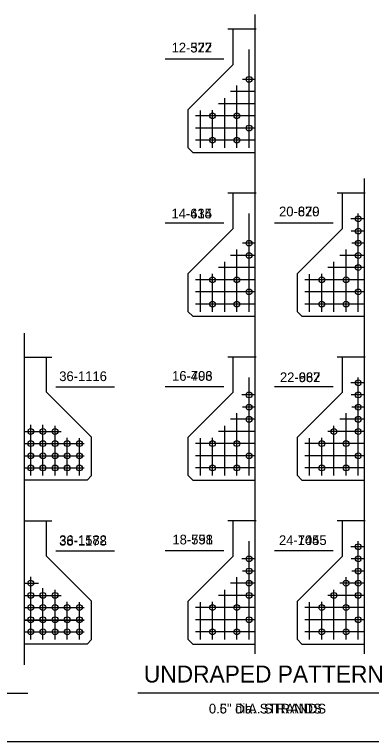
# Model space of a CAD drawing. Extents: x 1005.3 to 1101.9, y 1996.5 to 2073.3.
# Drawn here: x 1025.64 to 1037.89, y 2012.16 to 2037.11 of the extents above; entities that cross this region are included whole.
import ezdxf

# ---------------------------------------------------------------- set-up
doc = ezdxf.new("R2010")
doc.units = 0
for name, color, linetype in [('Level 1', 7, 'Continuous'), ('Level 2', 7, 'Continuous'), ('Level 8', 7, 'Continuous'), ('Level 9', 7, 'Continuous')]:
    doc.layers.add(name, color=color, linetype=linetype)

msp = doc.modelspace()

# ---------------------------------------------------------------- linework, layer by layer
at = {"layer": 'Level 1'}
msp.add_line((1013.852, 2012.158), (1097.517, 2012.158), dxfattribs=at)
at = {"layer": 'Level 2'}
for p, q in [((1017.555, 2013.82), (1026.098, 2013.82)), ((1039.275, 2013.82), (1029.876, 2013.82))]:
    msp.add_line(p, q, dxfattribs=at)
at = {"layer": 'Level 8'}
for p, q in [((1033.897, 2015.162), (1033.897, 2037.107)), ((1033.929, 2036.601), (1032.963, 2036.601)), ((1033.144, 2035.393), (1033.144, 2036.594)), ((1033.687, 2032.533), (1033.687, 2035.904)), ((1032.827, 2035.577), (1030.807, 2035.577)), ((1031.599, 2033.848), (1033.144, 2035.393)), ((1033.905, 2034.882), (1033.468, 2034.882)), ((1033.905, 2034.882), (1033.902, 2034.882)), ((1033.269, 2032.533), (1033.269, 2034.673)), ((1033.905, 2034.464), (1033.053, 2034.464)), ((1032.852, 2032.533), (1032.852, 2034.242)), ((1031.599, 2032.533), (1031.599, 2033.848)), ((1033.905, 2034.047), (1032.641, 2034.047)), ((1033.905, 2033.629), (1031.849, 2033.629)), ((1032.017, 2032.533), (1032.017, 2033.819)), ((1032.434, 2032.533), (1032.434, 2033.827)), ((1033.905, 2033.212), (1031.849, 2033.212)), ((1033.905, 2032.794), (1031.849, 2032.794)), ((1031.755, 2032.376), (1031.599, 2032.533)), ((1031.755, 2032.376), (1033.905, 2032.376)), ((1037.655, 2015.162), (1037.655, 2031.484)), ((1033.929, 2030.976), (1032.963, 2030.976)), ((1033.144, 2029.768), (1033.144, 2030.969)), ((1037.679, 2030.976), (1036.713, 2030.976)), ((1036.894, 2029.768), (1036.894, 2030.969)), ((1033.687, 2026.908), (1033.687, 2030.279)), ((1037.655, 2030.092), (1037.187, 2030.092)), ((1037.437, 2026.908), (1037.437, 2030.279)), ((1032.827, 2029.952), (1030.807, 2029.952)), ((1036.577, 2029.952), (1034.557, 2029.952)), ((1031.599, 2028.223), (1033.144, 2029.768)), ((1035.349, 2028.223), (1036.894, 2029.768)), ((1037.655, 2029.675), (1037.19, 2029.675)), ((1033.905, 2029.257), (1033.468, 2029.257)), ((1033.905, 2029.257), (1033.902, 2029.257)), ((1037.655, 2029.257), (1037.218, 2029.257)), ((1037.655, 2029.257), (1037.652, 2029.257)), ((1033.269, 2026.908), (1033.269, 2029.048)), ((1037.019, 2026.908), (1037.019, 2029.048)), ((1032.852, 2026.908), (1032.852, 2028.617)), ((1033.905, 2028.839), (1033.053, 2028.839)), ((1036.602, 2026.908), (1036.602, 2028.617)), ((1037.655, 2028.839), (1036.803, 2028.839)), ((1033.905, 2028.422), (1032.641, 2028.422)), ((1037.655, 2028.422), (1036.391, 2028.422)), ((1031.599, 2026.908), (1031.599, 2028.223)), ((1032.017, 2026.908), (1032.017, 2028.194)), ((1032.434, 2026.908), (1032.434, 2028.202)), ((1035.349, 2026.908), (1035.349, 2028.223)), ((1035.767, 2026.908), (1035.767, 2028.194)), ((1036.184, 2026.908), (1036.184, 2028.202)), ((1033.905, 2028.004), (1031.849, 2028.004)), ((1037.655, 2028.004), (1035.599, 2028.004)), ((1033.905, 2027.587), (1031.849, 2027.587)), ((1037.655, 2027.587), (1035.599, 2027.587)), ((1033.905, 2027.169), (1031.849, 2027.169)), ((1037.655, 2027.169), (1035.599, 2027.169)), ((1031.755, 2026.751), (1031.599, 2026.908)), ((1035.505, 2026.751), (1035.349, 2026.908)), ((1031.755, 2026.751), (1033.905, 2026.751)), ((1035.505, 2026.751), (1037.655, 2026.751)), ((1025.976, 2015.057), (1025.976, 2026.174)), ((1025.953, 2025.351), (1026.918, 2025.351)), ((1033.929, 2025.351), (1032.963, 2025.351)), ((1037.679, 2025.351), (1036.713, 2025.351)), ((1026.738, 2024.143), (1026.738, 2025.344)), ((1033.144, 2024.143), (1033.144, 2025.344)), ((1036.894, 2024.143), (1036.894, 2025.344)), ((1033.687, 2021.283), (1033.687, 2024.654)), ((1037.437, 2021.283), (1037.437, 2024.654)), ((1037.655, 2024.467), (1037.187, 2024.467)), ((1028.282, 2022.598), (1026.738, 2024.143)), ((1027.054, 2024.327), (1029.074, 2024.327)), ((1032.827, 2024.327), (1030.807, 2024.327)), ((1031.599, 2022.598), (1033.144, 2024.143)), ((1036.577, 2024.327), (1034.557, 2024.327)), ((1035.349, 2022.598), (1036.894, 2024.143)), ((1033.905, 2024.05), (1033.44, 2024.05)), ((1037.655, 2024.05), (1037.19, 2024.05)), ((1033.905, 2023.632), (1033.468, 2023.632)), ((1033.905, 2023.632), (1033.902, 2023.632)), ((1037.655, 2023.632), (1037.218, 2023.632)), ((1037.655, 2023.632), (1037.652, 2023.632)), ((1033.269, 2021.283), (1033.269, 2023.423)), ((1037.019, 2021.283), (1037.019, 2023.423)), ((1033.905, 2023.214), (1033.053, 2023.214)), ((1037.655, 2023.214), (1036.803, 2023.214)), ((1026.195, 2021.283), (1026.195, 2023.021)), ((1026.612, 2021.283), (1026.612, 2023.027)), ((1027.03, 2021.283), (1027.03, 2022.992)), ((1032.852, 2021.283), (1032.852, 2022.992)), ((1036.602, 2021.283), (1036.602, 2022.992)), ((1025.976, 2022.797), (1027.241, 2022.797)), ((1033.905, 2022.797), (1032.641, 2022.797)), ((1037.655, 2022.797), (1036.391, 2022.797)), ((1025.976, 2022.379), (1028.033, 2022.379)), ((1027.447, 2021.283), (1027.447, 2022.577)), ((1027.865, 2021.283), (1027.865, 2022.569)), ((1028.282, 2021.283), (1028.282, 2022.598)), ((1031.599, 2021.283), (1031.599, 2022.598)), ((1033.905, 2022.379), (1031.849, 2022.379)), ((1032.017, 2021.283), (1032.017, 2022.569)), ((1032.434, 2021.283), (1032.434, 2022.577)), ((1035.349, 2021.283), (1035.349, 2022.598)), ((1037.655, 2022.379), (1035.599, 2022.379)), ((1035.767, 2021.283), (1035.767, 2022.569)), ((1036.184, 2021.283), (1036.184, 2022.577)), ((1025.976, 2021.962), (1028.033, 2021.962)), ((1033.905, 2021.962), (1031.849, 2021.962)), ((1037.655, 2021.962), (1035.599, 2021.962)), ((1025.976, 2021.544), (1028.033, 2021.544)), ((1033.905, 2021.544), (1031.849, 2021.544)), ((1037.655, 2021.544), (1035.599, 2021.544)), ((1028.126, 2021.126), (1025.976, 2021.126)), ((1028.126, 2021.126), (1028.282, 2021.283)), ((1031.755, 2021.126), (1031.599, 2021.283)), ((1031.755, 2021.126), (1033.905, 2021.126)), ((1035.505, 2021.126), (1035.349, 2021.283)), ((1035.505, 2021.126), (1037.655, 2021.126)), ((1025.953, 2019.726), (1026.918, 2019.726)), ((1026.738, 2018.518), (1026.738, 2019.719)), ((1033.929, 2019.726), (1032.963, 2019.726)), ((1033.144, 2018.518), (1033.144, 2019.719)), ((1037.679, 2019.726), (1036.713, 2019.726)), ((1036.894, 2018.518), (1036.894, 2019.719)), ((1033.687, 2015.658), (1033.687, 2019.029)), ((1037.437, 2015.658), (1037.437, 2019.029)), ((1027.054, 2018.702), (1029.074, 2018.702)), ((1032.827, 2018.702), (1030.807, 2018.702)), ((1036.577, 2018.702), (1034.557, 2018.702)), ((1037.655, 2018.842), (1037.187, 2018.842)), ((1028.282, 2016.973), (1026.738, 2018.518)), ((1031.599, 2016.973), (1033.144, 2018.518)), ((1033.905, 2018.425), (1033.44, 2018.425)), ((1035.349, 2016.973), (1036.894, 2018.518)), ((1037.655, 2018.425), (1037.19, 2018.425)), ((1025.976, 2018.007), (1025.979, 2018.007)), ((1033.905, 2018.007), (1033.468, 2018.007)), ((1033.905, 2018.007), (1033.902, 2018.007)), ((1037.655, 2018.007), (1037.218, 2018.007)), ((1037.655, 2018.007), (1037.652, 2018.007)), ((1026.195, 2015.658), (1026.195, 2017.809)), ((1033.269, 2015.658), (1033.269, 2017.798)), ((1037.019, 2015.658), (1037.019, 2017.798)), ((1025.976, 2017.589), (1026.463, 2017.589)), ((1026.612, 2015.658), (1026.612, 2017.418)), ((1027.03, 2015.658), (1027.03, 2017.367)), ((1032.852, 2015.658), (1032.852, 2017.367)), ((1033.905, 2017.589), (1033.053, 2017.589)), ((1036.602, 2015.658), (1036.602, 2017.367)), ((1037.655, 2017.589), (1036.803, 2017.589)), ((1025.976, 2017.172), (1027.241, 2017.172)), ((1033.905, 2017.172), (1032.641, 2017.172)), ((1037.655, 2017.172), (1036.391, 2017.172)), ((1027.447, 2015.658), (1027.447, 2016.952)), ((1027.865, 2015.658), (1027.865, 2016.944)), ((1028.282, 2015.658), (1028.282, 2016.973)), ((1031.599, 2015.658), (1031.599, 2016.973)), ((1032.017, 2015.658), (1032.017, 2016.944)), ((1032.434, 2015.658), (1032.434, 2016.952)), ((1035.349, 2015.658), (1035.349, 2016.973)), ((1035.767, 2015.658), (1035.767, 2016.944)), ((1036.184, 2015.658), (1036.184, 2016.952)), ((1025.976, 2016.754), (1028.033, 2016.754)), ((1033.905, 2016.754), (1031.849, 2016.754)), ((1037.655, 2016.754), (1035.599, 2016.754)), ((1025.976, 2016.337), (1028.033, 2016.337)), ((1025.976, 2016.32), (1028.033, 2016.32)), ((1033.905, 2016.337), (1031.849, 2016.337)), ((1037.655, 2016.337), (1035.599, 2016.337)), ((1025.976, 2015.919), (1028.033, 2015.919)), ((1033.905, 2015.919), (1031.849, 2015.919)), ((1037.655, 2015.919), (1035.599, 2015.919)), ((1028.126, 2015.501), (1028.282, 2015.658)), ((1031.755, 2015.501), (1031.599, 2015.658)), ((1035.505, 2015.501), (1035.349, 2015.658)), ((1028.126, 2015.501), (1025.976, 2015.501)), ((1031.755, 2015.501), (1033.905, 2015.501)), ((1035.505, 2015.501), (1037.655, 2015.501))]:
    msp.add_line(p, q, dxfattribs=at)
for centre in [(1033.687, 2034.882), (1032.434, 2033.629), (1033.269, 2033.629), (1033.687, 2033.212), (1032.434, 2032.794), (1033.269, 2032.794), (1037.437, 2030.092), (1037.437, 2029.675), (1033.687, 2029.257), (1037.437, 2029.257), (1033.687, 2028.839), (1037.437, 2028.839), (1037.437, 2028.422), (1032.434, 2028.004), (1033.269, 2028.004), (1036.184, 2028.004), (1037.019, 2028.004), (1033.687, 2027.587), (1037.437, 2027.587), (1032.434, 2027.169), (1033.269, 2027.169), (1036.184, 2027.169), (1037.019, 2027.169), (1037.437, 2024.467), (1033.687, 2024.05), (1037.437, 2024.05), (1033.687, 2023.632), (1037.437, 2023.632), (1033.687, 2023.214), (1037.437, 2023.214), (1026.195, 2022.797), (1026.612, 2022.797), (1027.03, 2022.797), (1036.602, 2022.797), (1037.437, 2022.797), (1026.195, 2022.379), (1026.612, 2022.379), (1027.03, 2022.379), (1027.447, 2022.379), (1027.865, 2022.379), (1032.434, 2022.379), (1033.269, 2022.379), (1036.184, 2022.379), (1037.019, 2022.379), (1026.195, 2021.962), (1026.612, 2021.962), (1027.03, 2021.962), (1027.447, 2021.962), (1027.865, 2021.962), (1033.687, 2021.962), (1037.437, 2021.962), (1026.195, 2021.544), (1026.612, 2021.544), (1027.03, 2021.544), (1027.447, 2021.544), (1027.865, 2021.544), (1032.434, 2021.544), (1033.269, 2021.544), (1036.184, 2021.544), (1037.019, 2021.544), (1037.437, 2018.842), (1033.687, 2018.425), (1037.437, 2018.425), (1033.687, 2018.007), (1037.437, 2018.007), (1026.195, 2017.589), (1033.687, 2017.589), (1037.019, 2017.589), (1037.437, 2017.589), (1026.195, 2017.172), (1026.612, 2017.172), (1027.03, 2017.172), (1033.687, 2017.172), (1036.602, 2017.172), (1037.437, 2017.172), (1026.195, 2016.754), (1026.612, 2016.754), (1027.03, 2016.754), (1027.447, 2016.754), (1027.865, 2016.754), (1032.434, 2016.754), (1033.269, 2016.754), (1036.184, 2016.754), (1037.019, 2016.754), (1026.195, 2016.337), (1026.612, 2016.337), (1027.03, 2016.337), (1027.447, 2016.337), (1027.865, 2016.337), (1033.687, 2016.337), (1037.437, 2016.337), (1026.195, 2015.919), (1026.612, 2015.919), (1027.03, 2015.919), (1027.447, 2015.919), (1027.865, 2015.919), (1032.434, 2015.919), (1033.269, 2015.919), (1036.184, 2015.919), (1037.019, 2015.919)]:
    msp.add_circle(centre, 0.0996, dxfattribs=at)
at = {"layer": 'Level 9'}
for p, q in [((1033.897, 2015.162), (1033.897, 2037.107)), ((1033.929, 2036.601), (1032.963, 2036.601)), ((1033.144, 2035.393), (1033.144, 2036.594)), ((1033.687, 2032.533), (1033.687, 2035.904)), ((1032.827, 2035.577), (1030.807, 2035.577)), ((1031.599, 2033.848), (1033.144, 2035.393)), ((1033.905, 2034.882), (1033.468, 2034.882)), ((1033.905, 2034.882), (1033.902, 2034.882)), ((1033.269, 2032.533), (1033.269, 2034.673)), ((1033.905, 2034.464), (1033.053, 2034.464)), ((1032.852, 2032.533), (1032.852, 2034.242)), ((1031.599, 2032.533), (1031.599, 2033.848)), ((1033.905, 2034.047), (1032.641, 2034.047)), ((1033.905, 2033.629), (1031.849, 2033.629)), ((1032.017, 2032.533), (1032.017, 2033.819)), ((1032.434, 2032.533), (1032.434, 2033.827)), ((1033.905, 2033.212), (1031.849, 2033.212)), ((1033.905, 2032.794), (1031.849, 2032.794)), ((1031.755, 2032.376), (1031.599, 2032.533)), ((1031.755, 2032.376), (1033.905, 2032.376)), ((1037.655, 2015.162), (1037.655, 2031.484)), ((1033.929, 2030.976), (1032.963, 2030.976)), ((1033.144, 2029.768), (1033.144, 2030.969)), ((1037.679, 2030.976), (1036.713, 2030.976)), ((1036.894, 2029.768), (1036.894, 2030.969)), ((1033.687, 2026.908), (1033.687, 2030.279)), ((1037.655, 2030.092), (1037.187, 2030.092)), ((1037.437, 2026.908), (1037.437, 2030.279)), ((1032.827, 2029.952), (1030.807, 2029.952)), ((1036.577, 2029.952), (1034.557, 2029.952)), ((1031.599, 2028.223), (1033.144, 2029.768)), ((1035.349, 2028.223), (1036.894, 2029.768)), ((1037.655, 2029.675), (1037.19, 2029.675)), ((1033.905, 2029.257), (1033.468, 2029.257)), ((1033.905, 2029.257), (1033.902, 2029.257)), ((1037.655, 2029.257), (1037.218, 2029.257)), ((1037.655, 2029.257), (1037.652, 2029.257)), ((1033.269, 2026.908), (1033.269, 2029.048)), ((1037.019, 2026.908), (1037.019, 2029.048)), ((1032.852, 2026.908), (1032.852, 2028.617)), ((1033.905, 2028.839), (1033.053, 2028.839)), ((1036.602, 2026.908), (1036.602, 2028.617)), ((1037.655, 2028.839), (1036.803, 2028.839)), ((1033.905, 2028.422), (1032.641, 2028.422)), ((1037.655, 2028.422), (1036.391, 2028.422)), ((1031.599, 2026.908), (1031.599, 2028.223)), ((1032.017, 2026.908), (1032.017, 2028.194)), ((1032.434, 2026.908), (1032.434, 2028.202)), ((1035.349, 2026.908), (1035.349, 2028.223)), ((1035.767, 2026.908), (1035.767, 2028.194)), ((1036.184, 2026.908), (1036.184, 2028.202)), ((1033.905, 2028.004), (1031.849, 2028.004)), ((1037.655, 2028.004), (1035.599, 2028.004)), ((1033.905, 2027.587), (1031.849, 2027.587)), ((1037.655, 2027.587), (1035.599, 2027.587)), ((1033.905, 2027.169), (1031.849, 2027.169)), ((1037.655, 2027.169), (1035.599, 2027.169)), ((1031.755, 2026.751), (1031.599, 2026.908)), ((1035.505, 2026.751), (1035.349, 2026.908)), ((1031.755, 2026.751), (1033.905, 2026.751)), ((1035.505, 2026.751), (1037.655, 2026.751)), ((1033.929, 2025.351), (1032.963, 2025.351)), ((1037.679, 2025.351), (1036.713, 2025.351)), ((1033.144, 2024.143), (1033.144, 2025.344)), ((1036.894, 2024.143), (1036.894, 2025.344)), ((1033.687, 2021.283), (1033.687, 2024.654)), ((1037.437, 2021.283), (1037.437, 2024.654)), ((1037.655, 2024.467), (1037.187, 2024.467)), ((1032.827, 2024.327), (1030.807, 2024.327)), ((1031.599, 2022.598), (1033.144, 2024.143)), ((1036.577, 2024.327), (1034.557, 2024.327)), ((1035.349, 2022.598), (1036.894, 2024.143)), ((1033.905, 2024.05), (1033.44, 2024.05)), ((1037.655, 2024.05), (1037.19, 2024.05)), ((1033.905, 2023.632), (1033.468, 2023.632)), ((1033.905, 2023.632), (1033.902, 2023.632)), ((1037.655, 2023.632), (1037.218, 2023.632)), ((1037.655, 2023.632), (1037.652, 2023.632)), ((1033.269, 2021.283), (1033.269, 2023.423)), ((1037.019, 2021.283), (1037.019, 2023.423)), ((1033.905, 2023.214), (1033.053, 2023.214)), ((1037.655, 2023.214), (1036.803, 2023.214)), ((1032.852, 2021.283), (1032.852, 2022.992)), ((1036.602, 2021.283), (1036.602, 2022.992)), ((1033.905, 2022.797), (1032.641, 2022.797)), ((1037.655, 2022.797), (1036.391, 2022.797)), ((1031.599, 2021.283), (1031.599, 2022.598)), ((1033.905, 2022.379), (1031.849, 2022.379)), ((1032.017, 2021.283), (1032.017, 2022.569)), ((1032.434, 2021.283), (1032.434, 2022.577)), ((1035.349, 2021.283), (1035.349, 2022.598)), ((1037.655, 2022.379), (1035.599, 2022.379)), ((1035.767, 2021.283), (1035.767, 2022.569)), ((1036.184, 2021.283), (1036.184, 2022.577)), ((1033.905, 2021.962), (1031.849, 2021.962)), ((1037.655, 2021.962), (1035.599, 2021.962)), ((1033.905, 2021.544), (1031.849, 2021.544)), ((1037.655, 2021.544), (1035.599, 2021.544)), ((1031.755, 2021.126), (1031.599, 2021.283)), ((1031.755, 2021.126), (1033.905, 2021.126)), ((1035.505, 2021.126), (1035.349, 2021.283)), ((1035.505, 2021.126), (1037.655, 2021.126)), ((1025.976, 2014.784), (1025.976, 2020.549)), ((1025.953, 2019.726), (1026.918, 2019.726)), ((1026.738, 2018.518), (1026.738, 2019.719)), ((1033.929, 2019.726), (1032.963, 2019.726)), ((1033.144, 2018.518), (1033.144, 2019.719)), ((1037.679, 2019.726), (1036.713, 2019.726)), ((1036.894, 2018.518), (1036.894, 2019.719)), ((1033.687, 2015.658), (1033.687, 2019.029)), ((1037.437, 2015.658), (1037.437, 2019.029)), ((1027.054, 2018.702), (1029.074, 2018.702)), ((1032.827, 2018.702), (1030.807, 2018.702)), ((1036.577, 2018.702), (1034.557, 2018.702)), ((1037.655, 2018.842), (1037.187, 2018.842)), ((1028.282, 2016.973), (1026.738, 2018.518)), ((1031.599, 2016.973), (1033.144, 2018.518)), ((1033.905, 2018.425), (1033.44, 2018.425)), ((1035.349, 2016.973), (1036.894, 2018.518)), ((1037.655, 2018.425), (1037.19, 2018.425)), ((1033.905, 2018.007), (1033.468, 2018.007)), ((1033.905, 2018.007), (1033.902, 2018.007)), ((1037.655, 2018.007), (1037.218, 2018.007)), ((1037.655, 2018.007), (1037.652, 2018.007)), ((1033.269, 2015.658), (1033.269, 2017.798)), ((1037.019, 2015.658), (1037.019, 2017.798)), ((1026.195, 2015.658), (1026.195, 2017.396)), ((1026.612, 2015.658), (1026.612, 2017.402)), ((1027.03, 2015.658), (1027.03, 2017.367)), ((1032.852, 2015.658), (1032.852, 2017.367)), ((1033.905, 2017.589), (1033.053, 2017.589)), ((1036.602, 2015.658), (1036.602, 2017.367)), ((1037.655, 2017.589), (1036.803, 2017.589)), ((1025.976, 2017.172), (1027.241, 2017.172)), ((1033.905, 2017.172), (1032.641, 2017.172)), ((1037.655, 2017.172), (1036.391, 2017.172)), ((1027.447, 2015.658), (1027.447, 2016.952)), ((1027.865, 2015.658), (1027.865, 2016.944)), ((1028.282, 2015.658), (1028.282, 2016.973)), ((1031.599, 2015.658), (1031.599, 2016.973)), ((1032.017, 2015.658), (1032.017, 2016.944)), ((1032.434, 2015.658), (1032.434, 2016.952)), ((1035.349, 2015.658), (1035.349, 2016.973)), ((1035.767, 2015.658), (1035.767, 2016.944)), ((1036.184, 2015.658), (1036.184, 2016.952)), ((1025.976, 2016.754), (1028.033, 2016.754)), ((1033.905, 2016.754), (1031.849, 2016.754)), ((1037.655, 2016.754), (1035.599, 2016.754)), ((1025.976, 2016.337), (1028.033, 2016.337)), ((1033.905, 2016.337), (1031.849, 2016.337)), ((1037.655, 2016.337), (1035.599, 2016.337)), ((1025.976, 2015.919), (1028.033, 2015.919)), ((1033.905, 2015.919), (1031.849, 2015.919)), ((1037.655, 2015.919), (1035.599, 2015.919)), ((1028.126, 2015.501), (1028.282, 2015.658)), ((1031.755, 2015.501), (1031.599, 2015.658)), ((1035.505, 2015.501), (1035.349, 2015.658)), ((1028.126, 2015.501), (1025.976, 2015.501)), ((1031.755, 2015.501), (1033.905, 2015.501)), ((1035.505, 2015.501), (1037.655, 2015.501))]:
    msp.add_line(p, q, dxfattribs=at)
for centre in [(1033.687, 2034.882), (1032.434, 2033.629), (1033.269, 2033.629), (1033.687, 2033.212), (1032.434, 2032.794), (1033.269, 2032.794), (1037.437, 2030.092), (1037.437, 2029.675), (1033.687, 2029.257), (1037.437, 2029.257), (1033.687, 2028.839), (1037.437, 2028.839), (1037.437, 2028.422), (1032.434, 2028.004), (1033.269, 2028.004), (1036.184, 2028.004), (1037.019, 2028.004), (1033.687, 2027.587), (1037.437, 2027.587), (1032.434, 2027.169), (1033.269, 2027.169), (1036.184, 2027.169), (1037.019, 2027.169), (1037.437, 2024.467), (1033.687, 2024.05), (1037.437, 2024.05), (1033.687, 2023.632), (1037.437, 2023.632), (1033.687, 2023.214), (1037.437, 2023.214), (1036.602, 2022.797), (1037.437, 2022.797), (1032.434, 2022.379), (1033.269, 2022.379), (1036.184, 2022.379), (1037.019, 2022.379), (1033.687, 2021.962), (1037.437, 2021.962), (1032.434, 2021.544), (1033.269, 2021.544), (1036.184, 2021.544), (1037.019, 2021.544), (1037.437, 2018.842), (1033.687, 2018.425), (1037.437, 2018.425), (1033.687, 2018.007), (1037.437, 2018.007), (1033.687, 2017.589), (1037.019, 2017.589), (1037.437, 2017.589), (1026.195, 2017.172), (1026.612, 2017.172), (1027.03, 2017.172), (1033.687, 2017.172), (1036.602, 2017.172), (1037.437, 2017.172), (1026.195, 2016.754), (1026.612, 2016.754), (1027.03, 2016.754), (1027.447, 2016.754), (1027.865, 2016.754), (1032.434, 2016.754), (1033.269, 2016.754), (1036.184, 2016.754), (1037.019, 2016.754), (1026.195, 2016.337), (1026.612, 2016.337), (1027.03, 2016.337), (1027.447, 2016.337), (1027.865, 2016.337), (1033.687, 2016.337), (1037.437, 2016.337), (1026.195, 2015.919), (1026.612, 2015.919), (1027.03, 2015.919), (1027.447, 2015.919), (1027.865, 2015.919), (1032.434, 2015.919), (1033.269, 2015.919), (1036.184, 2015.919), (1037.019, 2015.919)]:
    msp.add_circle(centre, 0.0996, dxfattribs=at)

# ---------------------------------------------------------------- texts
at = {"layer": 'Level 2'}
msp.add_text('UNDRAPED PATTERN', height=0.58333, dxfattribs=at).set_placement((1030.078, 2014.181))
at = {"layer": 'Level 8'}
for s, height, p in [('12-372', 0.3333, (1031.029, 2035.805)), ('14-434', 0.3333, (1031.025, 2030.11)), ('20-620', 0.3333, (1034.718, 2030.181)), ('36-1116', 0.3333, (1027.173, 2024.526)), ('16-496', 0.3333, (1031.046, 2024.537)), ('22-682', 0.3333, (1034.748, 2024.491)), ('38-1178', 0.3333, (1027.17, 2018.88)), ('18-558', 0.3333, (1031.058, 2018.921)), ('24-744', 0.3333, (1034.715, 2018.9)), ('0.5" dia. STRANDS', 0.33333, (1032.309, 2013.119))]:
    msp.add_text(s, height=height, dxfattribs=at).set_placement(p)
at = {"layer": 'Level 9'}
for s, height, p in [('12-527', 0.3333, (1031.029, 2035.805)), ('14-615', 0.3333, (1031.025, 2030.11)), ('20-879', 0.3333, (1034.718, 2030.181)), ('16-703', 0.3333, (1031.046, 2024.537)), ('22-967', 0.3333, (1034.748, 2024.491)), ('36-1582', 0.3333, (1027.173, 2018.901)), ('18-791', 0.3333, (1031.058, 2018.921)), ('24-1055', 0.3333, (1034.715, 2018.9)), ('0.6" DIA. STRANDS', 0.33333, (1032.309, 2013.119))]:
    msp.add_text(s, height=height, dxfattribs=at).set_placement(p)

doc.saveas('drawing.dxf')
